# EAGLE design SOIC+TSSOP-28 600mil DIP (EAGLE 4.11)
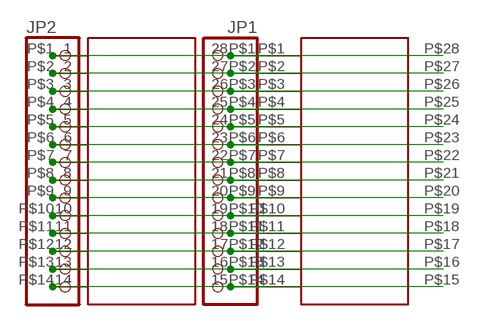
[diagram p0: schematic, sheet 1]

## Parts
JP1  PINHD-1X14THIN  [HEADER1X14]
JP2  PINHD-1X14THIN  [HEADER1X14]
U$1  SMD-28SOIC  [SO-28NMW]
U$2  SMD-28TSSOP  [TSSOP-28NM]

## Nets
N$1: JP2.P$14 U$1.P$15 U$2.14
N$2: JP2.P$13 U$1.P$16 U$2.13
N$3: JP2.P$12 U$1.P$17 U$2.12
N$4: JP2.P$11 U$1.P$18 U$2.11
N$5: JP2.P$10 U$1.P$19 U$2.10
N$6: JP2.P$9 U$1.P$20 U$2.9
N$7: JP2.P$8 U$1.P$21 U$2.8
N$8: JP2.P$7 U$1.P$22 U$2.7
N$9: JP2.P$6 U$1.P$23 U$2.6
N$10: JP2.P$5 U$1.P$24 U$2.5
N$11: JP2.P$4 U$1.P$25 U$2.4
N$12: JP2.P$3 U$1.P$26 U$2.3
N$13: JP2.P$2 U$1.P$27 U$2.2
N$14: JP2.P$1 U$1.P$28 U$2.1
N$15: JP1.P$1 U$1.P$1 U$2.28
N$16: JP1.P$2 U$1.P$2 U$2.27
N$17: JP1.P$3 U$1.P$3 U$2.26
N$18: JP1.P$4 U$1.P$4 U$2.25
N$19: JP1.P$5 U$1.P$5 U$2.24
N$20: JP1.P$6 U$1.P$6 U$2.23
N$21: JP1.P$7 U$1.P$7 U$2.22
N$22: JP1.P$8 U$1.P$8 U$2.21
N$23: JP1.P$9 U$1.P$9 U$2.20
N$24: JP1.P$10 U$1.P$10 U$2.19
N$25: JP1.P$11 U$1.P$11 U$2.18
N$26: JP1.P$12 U$1.P$12 U$2.17
N$27: JP1.P$13 U$1.P$13 U$2.16
N$28: JP1.P$14 U$1.P$14 U$2.15

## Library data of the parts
JP1 JP2 = boogie:PINHD-1X14: PIN HEADER
U$1 U$2 = boogie:SMD-28

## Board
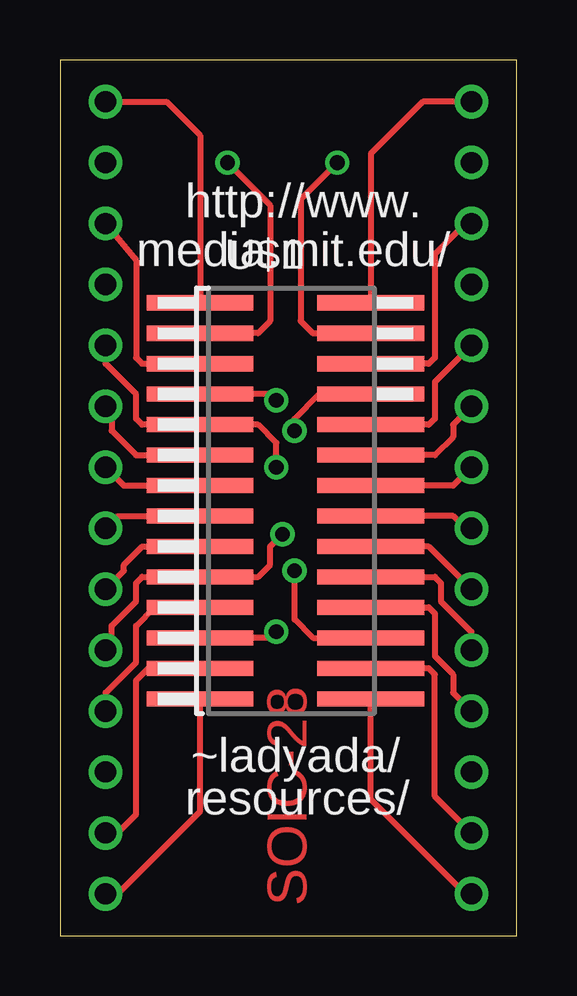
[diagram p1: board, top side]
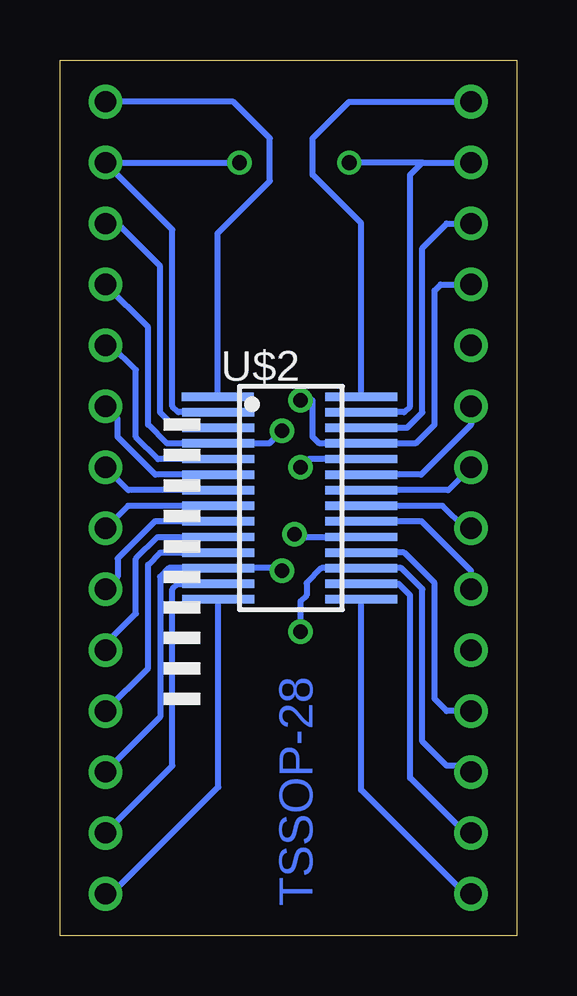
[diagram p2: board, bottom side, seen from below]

Size 19.03 x 36.5 mm. Coordinates in mm from the lower left corner, seen from the top.
Outline: 0,0 19.03,0 19.03,36.5 0,36.5 0,0
Copper layers (1*16): Top 0.035mm / dielectric 1.5mm / Bottom 0.035mm
Design rules "default": minimum track width 10mil, minimum drill 24mil, track to track 10mil, track to pad 10mil, pad to pad 10mil, via to via 10mil, smd to smd 8mil, copper to edge 40mil, drill to drill 8mil, minimum pad ring 10mil, minimum via ring 8mil, stop-mask expansion 4mil, vias tented up to drill 0mil, thermal gap 10mil

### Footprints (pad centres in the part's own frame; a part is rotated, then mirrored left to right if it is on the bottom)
HEADER1X14 = drill 0.889 round: P$1 13.97,0; P$2 11.43,0; P$3 8.89,0; P$4 6.35,0; P$5 3.81,0; P$6 1.27,0; P$7 -1.27,0; P$8 -3.81,0; P$9 -6.35,0; P$10 -8.89,0; P$11 -11.43,0; P$12 -13.97,0; P$13 -16.51,0; P$14 -19.05,0
SO-28NMW = smd 0.635 x 4.445: P$1 -6.858,-3.683; P$2 -5.588,-3.683; P$3 -4.318,-3.683; P$4 -3.048,-3.683; P$5 -1.778,-3.683; P$6 -0.508,-3.683; P$7 0.762,-3.683; P$8 2.032,-3.683; P$9 3.302,-3.683; P$10 4.572,-3.683; P$11 5.842,-3.683; P$12 7.112,-3.683; P$13 8.382,-3.683; P$14 9.652,-3.683; P$15 9.652,3.429; P$16 8.382,3.429; P$17 7.112,3.429; P$18 5.842,3.429; P$19 4.572,3.429; P$20 3.302,3.429; P$21 2.032,3.429; P$22 0.762,3.429; P$23 -0.508,3.429; P$24 -1.778,3.429; P$25 -3.048,3.429; P$26 -4.318,3.429; P$27 -5.588,3.429; P$28 -6.858,3.429
TSSOP-28NM = smd 0.35 x 3: 1 -3.695,-3.193; 2 -3.055,-3.169; 3 -2.405,-3.169; 4 -1.755,-3.169; 5 -1.105,-3.169; 6 -0.455,-3.169; 7 0.195,-3.169; 8 0.845,-3.169; 9 1.495,-3.169; 10 2.145,-3.169; 11 2.795,-3.169; 12 3.445,-3.169; 13 4.095,-3.169; 14 4.745,-3.169; 15 4.745,2.781; 16 4.095,2.781; 17 3.445,2.781; 18 2.795,2.781; 19 2.145,2.781; 20 1.495,2.781; 21 0.845,2.781; 22 0.195,2.781; 23 -0.455,2.781; 24 -1.105,2.781; 25 -1.755,2.781; 26 -2.405,2.781; 27 -3.055,2.781; 28 -3.705,2.781

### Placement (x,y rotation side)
JP1  1.9,20.79 90 top
JP2  17.14,20.79 90 top
U$1  9.52,19.52 270 top
U$2  9.27,18.76 270 bottom

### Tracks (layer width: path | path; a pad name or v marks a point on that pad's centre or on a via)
N$1
  Top 0.254: JP2.P$14 16.89,1.74 12.95,5.68 U$1.P$15
  Bottom 0.254: U$2.14 12.44,6.19 16.89,1.74 JP2.P$14
N$2
  Top 0.254: U$1.P$16 15.36,11.14 15.62,10.88 15.62,5.8 JP2.P$13
  Bottom 0.254: U$2.13 14.12,14.66 14.35,14.44 14.35,7.07 JP2.P$13
N$3  (via drill 0.61)
  Top 0.254: v9.77,15.2 9.77,13.17 10.54,12.41 U$1.P$17
  Bottom 0.254: JP2.P$12 14.85,9.11 14.85,14.95 14.49,15.31 U$2.12 9.89,15.31 v9.77,15.2
N$4
  Top 0.254: U$1.P$18 15.36,13.68 15.62,13.42 15.62,11.65 16.38,10.88 16.38,10.12 JP2.P$11
  Bottom 0.254: U$2.11 14.86,15.96 15.36,15.46 15.36,11.14 JP2.P$11
N$5
  Top 0.254: U$1.P$19 15.62,14.95 15.87,14.69 15.87,13.93 17.14,12.66 JP2.P$10
  Bottom 0.254: U$2.10 14.97,16.61 15.87,15.71 15.87,13.42 17.14,12.15 JP2.P$10
N$6
  Top 0.254: U$1.P$20 15.36,16.22 JP2.P$9
  Bottom 0.254: U$2.9 15.08,17.26 16.63,15.71 16.63,14.95 JP2.P$9
N$7
  Top 0.254: JP2.P$8 17.14,16.73 16.38,17.49 U$1.P$21
  Bottom 0.254: U$2.8 16.21,17.91 JP2.P$8
N$8
  Top 0.254: U$1.P$22 16.38,18.76 JP2.P$7
  Bottom 0.254: U$2.7 16.18,18.56 JP2.P$7
N$9
  Top 0.254: U$1.P$23 15.62,20.03 16.38,20.79 16.38,21.3 JP2.P$6
  Bottom 0.254: U$2.6 15.06,19.21 16.63,20.79 16.63,21.55 JP2.P$6
N$10
  Top 0.254: U$1.P$24 15.36,21.3 15.62,21.55 15.62,23.08 JP2.P$5
  Bottom 0.254: U$2.5 14.94,19.86 15.87,20.79 15.87,23.58 16.89,24.6 JP2.P$5
N$11  (via drill 0.61)
  Top 0.254: v9.77,21.04 9.77,21.55 10.79,22.57 U$1.P$25 13.08,22.57
  Bottom 0.254: JP2.P$4 15.36,25.36 15.36,21.3 14.58,20.51 U$2.4 10.31,20.51 v9.77,21.04
N$12
  Top 0.254: U$1.P$26 15.36,23.84 15.62,24.09 15.62,28.41 16.89,29.68 JP2.P$3
  Bottom 0.254: U$2.3 14.21,21.16 14.85,21.81 14.85,27.9 16.63,29.68 JP2.P$3
N$13  (via drill 0.61)
  Top 0.254: U$1.P$27 10.54,25.11 10.03,25.62 10.03,30.7 v11.55,32.22
  Bottom 0.254: v11.55,32.22 JP2.P$2 14.35,29.43 14.35,22.06 14.1,21.81 U$2.2
N$14
  Top 0.254: U$1.P$28 12.95,32.6 15.11,34.76 JP2.P$1
  Bottom 0.254: U$2.1 12.46,29.28 10.28,31.46 10.28,33.24 11.81,34.76 JP2.P$1
N$15
  Top 0.254: U$1.P$1 5.84,33.36 4.44,34.76 JP1.P$1
  Bottom 0.254: U$2.28 6.49,29.69 8.5,31.71 8.5,33.24 6.98,34.76 JP1.P$1
N$16  (via drill 0.61)
  Top 0.254: U$1.P$2 8.25,25.11 8.76,25.62 8.76,30.44 v6.98,32.22
  Bottom 0.254: 3.93,32.22 JP1.P$2 | 3.93,32.22 v6.98,32.22 | U$2.27 4.69,21.81 4.44,22.06 4.44,31.71 3.93,32.22
N$17
  Top 0.254: U$1.P$3 3.42,23.84 3.17,24.09 3.17,28.16 JP1.P$3
  Bottom 0.254: U$2.26 4.58,21.16 3.93,21.81 3.93,28.66 2.92,29.68 JP1.P$3
N$18  (via drill 0.61)
  Top 0.254: v9.01,22.31 8.76,22.57 U$1.P$4
  Bottom 0.254: JP1.P$4 3.17,27.14 3.42,26.89 3.42,21.3 4.21,20.51 U$2.25 8.23,20.51 8.5,20.79 8.5,22.31 v9.01,22.31
N$19  (via drill 0.61)
  Top 0.254: JP1.P$5 1.9,23.84 3.17,22.57 3.17,21.55 3.42,21.3 U$1.P$5 8.25,21.3 9.01,20.54 v9.01,19.52
  Bottom 0.254: U$2.24 8.67,19.86 v9.01,19.52
N$20
  Top 0.254: U$1.P$6 3.17,20.03 2.15,21.04 2.15,21.81 JP1.P$6
  Bottom 0.254: JP1.P$6 1.9,21.3 3.98,19.21 U$2.23
N$21
  Top 0.254: U$1.P$7 2.66,18.76 JP1.P$7
  Bottom 0.254: U$2.22 2.86,18.56 JP1.P$7
N$22
  Top 0.254: U$1.P$8 2.41,17.49 JP1.P$8
  Bottom 0.254: JP1.P$8 2.15,16.98 3.09,17.91 U$2.21
N$23
  Top 0.254: U$1.P$9 3.42,16.22 2.66,15.46 2.66,15.2 JP1.P$9
  Bottom 0.254: U$2.20 3.96,17.26 1.9,15.2 JP1.P$9
N$24  (via drill 0.61)
  Top 0.254: JP1.P$10 2.15,12.15 2.15,12.92 3.17,13.93 3.17,14.69 3.42,14.95 U$1.P$10 8.25,14.95 8.76,15.46 8.76,16.22 v9.27,16.73
  Bottom 0.254: 9.01,16.47 v9.27,16.73 9.15,16.61 U$2.19
N$25
  Top 0.254: U$1.P$11 3.93,13.68 3.17,12.92 3.17,11.39 1.9,10.12 JP1.P$11
  Bottom 0.254: U$2.18 4.69,15.96 3.42,14.69 3.42,9.87 2.92,9.36 JP1.P$11
N$26  (via drill 0.61)
  Top 0.254: U$1.P$12 8.76,12.41 v9.01,12.66
  Bottom 0.254: JP1.P$12 2.15,7.07 2.92,7.07 3.93,8.09 3.93,14.44 4.8,15.31 U$2.17 8.14,15.31 8.76,14.69 8.76,14.19 9.01,13.93 v9.01,12.66
N$27
  Top 0.254: U$1.P$13 3.68,11.14 3.17,10.63 3.17,5.04 2.41,4.28 JP1.P$13
  Bottom 0.254: U$2.16 4.92,14.66 4.44,14.19 4.44,6.57 2.15,4.28 JP1.P$13
N$28
  Top 0.254: JP1.P$14 2.41,1.74 5.84,5.17 U$1.P$14
  Bottom 0.254: JP1.P$14 2.15,1.74 6.49,6.07 U$2.15

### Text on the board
Top: SOIC-28
Bottom: TSSOP-28
tPlace: http://www. | media.mit.edu/ | ~ladyada/ | resources/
